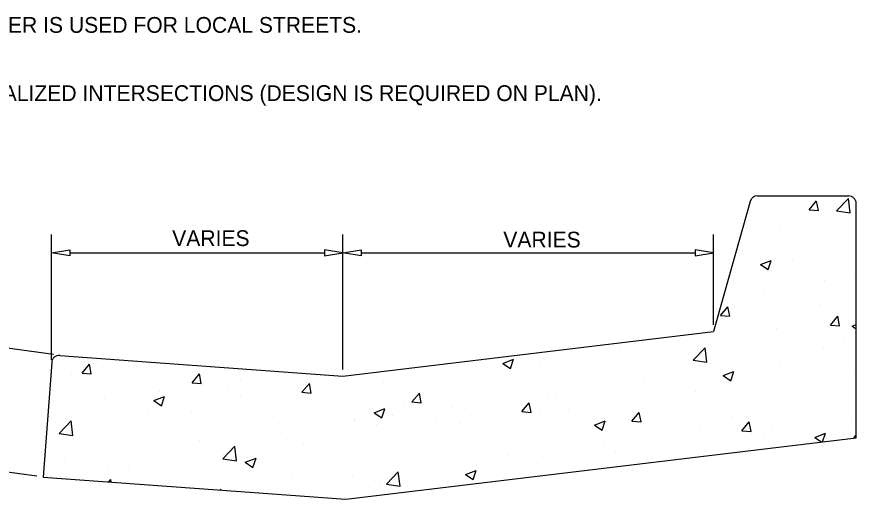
# Model space of a CAD drawing. Extents: x 6712067 to 6713867, y 1867712 to 1869162.
# Drawn here: x 6712266.7 to 6712585.9, y 1868583.6 to 1868767 of the extents above; entities that cross this region are included whole.
import ezdxf

# ---------------------------------------------------------------- set-up
doc = ezdxf.new("R2010")
doc.units = 0
for name, color, linetype in [('G-MARK', 7, 'Continuous'), ('G-TEXT', 7, 'Continuous'), ('Misc CnstDet(22)', 7, 'Continuous')]:
    doc.layers.add(name, color=color, linetype=linetype)

msp = doc.modelspace()

# ---------------------------------------------------------------- linework, layer by layer
at = {"layer": 'G-MARK'}
for p, q in [((6712279.92, 1868636.54), (6712279.92, 1868684.23)), ((6712390.72, 1868632.86), (6712390.72, 1868684.23)), ((6712531.74, 1868649.87), (6712531.74, 1868684.23)), ((6712286.92, 1868677.23), (6712383.72, 1868677.23)), ((6712397.72, 1868677.23), (6712524.74, 1868677.23)), ((6712280.72, 1868638.6), (6712254.9, 1868642.11)), ((6712274.41, 1868592.29), (6712248.59, 1868595.82))]:
    msp.add_line(p, q, dxfattribs=at)
at = {"layer": 'G-TEXT'}
for points in [[(6712286.92, 1868678.4), (6712286.92, 1868676.06), (6712279.92, 1868677.23)], [(6712383.72, 1868678.4), (6712383.72, 1868676.06), (6712390.72, 1868677.23)], [(6712397.72, 1868678.4), (6712397.72, 1868676.06), (6712390.72, 1868677.23)], [(6712524.74, 1868678.4), (6712524.74, 1868676.06), (6712531.74, 1868677.23)]]:
    msp.add_lwpolyline(points, close=True, dxfattribs=at)
at = {"layer": 'Misc CnstDet(22)'}
for p, q in [((6712548.37, 1868698.93), (6712583.03, 1868698.93)), ((6712578.48, 1868693.21), (6712583.03, 1868697.94)), ((6712583.67, 1868692.41), (6712583.03, 1868697.94)), ((6712545.57, 1868696.79), (6712531.73, 1868647.4)), ((6712551.38, 1868696.93), (6712551.38, 1868696.93)), ((6712568.08, 1868693.63), (6712570.88, 1868696.98)), ((6712571.57, 1868693.3), (6712570.88, 1868696.95)), ((6712585.94, 1868606.96), (6712585.94, 1868696.01)), ((6712568.08, 1868693.63), (6712571.57, 1868693.3)), ((6712578.48, 1868693.21), (6712583.67, 1868692.41)), ((6712557.14, 1868687.13), (6712557.14, 1868687.13)), ((6712390.72, 1868632.86), (6712390.72, 1868684.23)), ((6712571.21, 1868680.31), (6712571.21, 1868680.31)), ((6712572.86, 1868678.8), (6712572.86, 1868678.8)), ((6712390.72, 1868677.23), (6712390.72, 1868677.23)), ((6712531.74, 1868677.23), (6712531.74, 1868677.23)), ((6712549.56, 1868672.83), (6712553.65, 1868674.39)), ((6712549.56, 1868672.83), (6712552.45, 1868670.88)), ((6712552.45, 1868670.88), (6712553.65, 1868674.39)), ((6712561.61, 1868674.55), (6712561.61, 1868674.55)), ((6712542.79, 1868668.04), (6712542.79, 1868668.04)), ((6712556.43, 1868667.71), (6712556.43, 1868667.71)), ((6712573.89, 1868666.73), (6712573.89, 1868666.73)), ((6712585.18, 1868667.51), (6712585.18, 1868667.51)), ((6712551.19, 1868661.68), (6712551.19, 1868661.68)), ((6712534.37, 1868653.44), (6712537.17, 1868656.77)), ((6712537.83, 1868653.12), (6712537.17, 1868656.77)), ((6712572.1, 1868657.73), (6712572.1, 1868657.73)), ((6712534.37, 1868653.44), (6712537.83, 1868653.12)), ((6712557.5, 1868655.8), (6712557.5, 1868655.8)), ((6712576.16, 1868649.77), (6712578.99, 1868653.12)), ((6712579.65, 1868649.47), (6712578.99, 1868653.12)), ((6712576.16, 1868649.77), (6712579.65, 1868649.47)), ((6712584.36, 1868649.35), (6712585.94, 1868649.97)), ((6712585.64, 1868652.43), (6712585.64, 1868652.43)), ((6712390.72, 1868630.4), (6712531.73, 1868647.4)), ((6712531.74, 1868647.41), (6712531.74, 1868647.41)), ((6712555.71, 1868648.32), (6712555.71, 1868648.32)), ((6712584.36, 1868649.35), (6712585.94, 1868648.3)), ((6712525.44, 1868643.94), (6712525.44, 1868643.94)), ((6712550.02, 1868644.92), (6712550.02, 1868644.92)), ((6712581.12, 1868643.59), (6712581.12, 1868643.59)), ((6712496, 1868640.22), (6712496, 1868640.22)), ((6712524, 1868636.43), (6712528.54, 1868641.16)), ((6712529.18, 1868635.63), (6712528.54, 1868641.16)), ((6712573.45, 1868641.27), (6712573.45, 1868641.27)), ((6712283.12, 1868638.25), (6712390.72, 1868630.4)), ((6712283.13, 1868638.26), (6712283.13, 1868638.26)), ((6712578.85, 1868637.63), (6712578.85, 1868637.63)), ((6712280.03, 1868635.56), (6712276.84, 1868591.95)), ((6712279.92, 1868634.1), (6712279.92, 1868634.1)), ((6712291.57, 1868631.52), (6712294.37, 1868634.87)), ((6712295.06, 1868631.22), (6712294.37, 1868634.87)), ((6712299.24, 1868633.63), (6712299.24, 1868633.63)), ((6712317.39, 1868635.19), (6712317.39, 1868635.19)), ((6712451.58, 1868635.22), (6712455.67, 1868636.8)), ((6712451.58, 1868635.22), (6712454.5, 1868633.26)), ((6712454.5, 1868633.26), (6712455.67, 1868636.8)), ((6712466.07, 1868636.11), (6712466.07, 1868636.11)), ((6712524, 1868636.43), (6712529.18, 1868635.63)), ((6712539.46, 1868635.45), (6712539.46, 1868635.45)), ((6712556.77, 1868634.73), (6712556.77, 1868634.73)), ((6712287.46, 1868631.11), (6712287.46, 1868631.11)), ((6712291.57, 1868631.52), (6712295.06, 1868631.22)), ((6712333.39, 1868627.87), (6712336.19, 1868631.22)), ((6712336.88, 1868627.55), (6712336.19, 1868631.22)), ((6712373.71, 1868631.61), (6712373.71, 1868631.61)), ((6712435.77, 1868631.73), (6712435.77, 1868631.73)), ((6712535.38, 1868630.56), (6712539.46, 1868632.12)), ((6712535.38, 1868630.56), (6712538.27, 1868628.61)), ((6712538.27, 1868628.61), (6712539.46, 1868632.12)), ((6712542.17, 1868632.81), (6712542.17, 1868632.81)), ((6712584.93, 1868633.01), (6712584.93, 1868633.01)), ((6712333.39, 1868627.87), (6712336.88, 1868627.57)), ((6712351.63, 1868628.7), (6712351.63, 1868628.7)), ((6712375.2, 1868624.22), (6712378, 1868627.55)), ((6712378.67, 1868623.9), (6712378, 1868627.55)), ((6712390.72, 1868630.41), (6712390.72, 1868630.41)), ((6712390.72, 1868630.41), (6712390.72, 1868630.41)), ((6712406.33, 1868628.01), (6712406.33, 1868628.01)), ((6712505.36, 1868627.96), (6712505.36, 1868627.96)), ((6712505.45, 1868629.59), (6712505.45, 1868629.59)), ((6712555, 1868628.9), (6712555, 1868628.9)), ((6712289.71, 1868625.64), (6712289.71, 1868625.64)), ((6712320.83, 1868624.34), (6712320.83, 1868624.34)), ((6712337.06, 1868626.77), (6712337.06, 1868626.77)), ((6712347.2, 1868626.65), (6712347.2, 1868626.65)), ((6712375.2, 1868624.22), (6712378.67, 1868623.9)), ((6712483.28, 1868625.05), (6712483.28, 1868625.05)), ((6712524.73, 1868624.54), (6712524.73, 1868624.54)), ((6712300.22, 1868621.93), (6712300.22, 1868621.93)), ((6712318.84, 1868621.1), (6712322.92, 1868622.66)), ((6712318.84, 1868621.1), (6712321.73, 1868619.13)), ((6712321.73, 1868619.13), (6712322.92, 1868622.66)), ((6712351.93, 1868623.03), (6712351.93, 1868623.03)), ((6712376.4, 1868623.9), (6712376.4, 1868623.9)), ((6712383.05, 1868621.7), (6712383.05, 1868621.7)), ((6712417, 1868620.55), (6712419.82, 1868623.9)), ((6712420.49, 1868620.25), (6712419.82, 1868623.9)), ((6712468.68, 1868623.12), (6712468.68, 1868623.12)), ((6712471.46, 1868623.76), (6712471.46, 1868623.76)), ((6712301.99, 1868617.82), (6712301.99, 1868617.82)), ((6712313.21, 1868620.83), (6712313.21, 1868620.83)), ((6712346.13, 1868619.52), (6712346.13, 1868619.52)), ((6712402.61, 1868616.42), (6712406.69, 1868618)), ((6712405.52, 1868614.47), (6712406.69, 1868617.98)), ((6712414.17, 1868620.39), (6712414.17, 1868620.39)), ((6712417, 1868620.55), (6712420.49, 1868620.25)), ((6712431.87, 1868618.28), (6712431.87, 1868618.28)), ((6712437.47, 1868617.93), (6712437.47, 1868617.93)), ((6712445.3, 1868619.08), (6712445.3, 1868619.08)), ((6712458.81, 1868616.9), (6712461.64, 1868620.25)), ((6712462.3, 1868616.58), (6712461.64, 1868620.23)), ((6712476.42, 1868617.75), (6712476.42, 1868617.75)), ((6712495.28, 1868620.8), (6712495.28, 1868620.8)), ((6712279.2, 1868615), (6712279.2, 1868615)), ((6712316.68, 1868615.8), (6712316.68, 1868615.8)), ((6712333.11, 1868616.51), (6712333.11, 1868616.51)), ((6712364.23, 1868615.18), (6712364.23, 1868615.18)), ((6712402.61, 1868616.42), (6712405.52, 1868614.47)), ((6712409.79, 1868615.39), (6712409.79, 1868615.39)), ((6712458.81, 1868616.9), (6712462.3, 1868616.58)), ((6712465.36, 1868616.69), (6712465.36, 1868616.69)), ((6712500.63, 1868613.23), (6712503.45, 1868616.58)), ((6712504.12, 1868612.93), (6712503.45, 1868616.58)), ((6712507.54, 1868616.44), (6712507.54, 1868616.44)), ((6712538.66, 1868615.13), (6712538.66, 1868615.13)), ((6712563.52, 1868614.65), (6712563.52, 1868614.65)), ((6712282.85, 1868608.59), (6712287.39, 1868613.32)), ((6712286.75, 1868611.69), (6712286.75, 1868611.69)), ((6712288.04, 1868607.79), (6712287.39, 1868613.32)), ((6712395.19, 1868613.46), (6712395.19, 1868613.46)), ((6712395.35, 1868613.87), (6712395.35, 1868613.87)), ((6712403.46, 1868612.08), (6712403.46, 1868612.08)), ((6712426.48, 1868612.56), (6712426.48, 1868612.56)), ((6712435.08, 1868612.33), (6712435.08, 1868612.33)), ((6712486.4, 1868611.76), (6712490.46, 1868613.32)), ((6712486.4, 1868611.76), (6712489.29, 1868609.81)), ((6712489.29, 1868609.79), (6712490.46, 1868613.32)), ((6712500.63, 1868613.23), (6712504.12, 1868612.93)), ((6712541.44, 1868611.74), (6712541.44, 1868611.74)), ((6712542.45, 1868609.58), (6712545.25, 1868612.93)), ((6712545.94, 1868609.26), (6712545.25, 1868612.93)), ((6712569.78, 1868613.83), (6712569.78, 1868613.83)), ((6712584.22, 1868613.6), (6712584.22, 1868613.6)), ((6712282.85, 1868608.59), (6712288.04, 1868607.79)), ((6712358.38, 1868608.62), (6712358.38, 1868608.62)), ((6712405.64, 1868608.59), (6712405.64, 1868608.59)), ((6712457.6, 1868611.25), (6712457.6, 1868611.25)), ((6712488.72, 1868609.92), (6712488.72, 1868609.92)), ((6712519.84, 1868608.62), (6712519.84, 1868608.62)), ((6712526.84, 1868609.81), (6712526.84, 1868609.81)), ((6712542.45, 1868609.58), (6712545.94, 1868609.28)), ((6712554.29, 1868609.51), (6712554.29, 1868609.51)), ((6712570.17, 1868607.08), (6712574.26, 1868608.66)), ((6712573.18, 1868605.43), (6712574.26, 1868608.64)), ((6712336.3, 1868605.7), (6712336.3, 1868605.7)), ((6712369.47, 1868606.25), (6712369.47, 1868606.25)), ((6712391.82, 1868583.55), (6712585.94, 1868606.96)), ((6712490.03, 1868604.97), (6712490.03, 1868604.97)), ((6712524.02, 1868605.13), (6712524.02, 1868605.13)), ((6712550.94, 1868607.31), (6712550.94, 1868607.31)), ((6712570.17, 1868607.08), (6712572.72, 1868605.38)), ((6712571.04, 1868606.48), (6712571.04, 1868606.48)), ((6712585.04, 1868606.85), (6712585.94, 1868607.93)), ((6712321.71, 1868603.77), (6712321.71, 1868603.77)), ((6712345.07, 1868598.93), (6712349.61, 1868603.68)), ((6712350.26, 1868598.13), (6712349.61, 1868603.66)), ((6712375.69, 1868604.48), (6712375.69, 1868604.48)), ((6712467.95, 1868602.05), (6712467.95, 1868602.05)), ((6712284.89, 1868598.93), (6712284.89, 1868598.93)), ((6712335.48, 1868600.42), (6712335.48, 1868600.42)), ((6712345.07, 1868598.93), (6712350.26, 1868598.13)), ((6712345.41, 1868600.12), (6712345.41, 1868600.12)), ((6712353.63, 1868597.62), (6712357.72, 1868599.18)), ((6712356.52, 1868595.67), (6712357.72, 1868599.18)), ((6712453.35, 1868600.15), (6712453.35, 1868600.15)), ((6712494.57, 1868601.41), (6712494.57, 1868601.41)), ((6712278.1, 1868596.02), (6712278.1, 1868596.02)), ((6712315.97, 1868596.38), (6712315.97, 1868596.38)), ((6712353.63, 1868597.62), (6712356.52, 1868595.67)), ((6712464.64, 1868597.3), (6712464.64, 1868597.3)), ((6712286.04, 1868592.27), (6712286.04, 1868592.27)), ((6712301.49, 1868594.59), (6712301.49, 1868594.59)), ((6712309.22, 1868594.71), (6712309.22, 1868594.71)), ((6712340.34, 1868593.38), (6712340.34, 1868593.38)), ((6712394.46, 1868592.39), (6712394.46, 1868592.39)), ((6712407.29, 1868589.29), (6712411.83, 1868594.02)), ((6712412.48, 1868588.49), (6712411.83, 1868594.02)), ((6712416.54, 1868595.28), (6712416.54, 1868595.28)), ((6712434.37, 1868592.92), (6712434.37, 1868592.92)), ((6712437.4, 1868592.96), (6712441.49, 1868594.52)), ((6712437.4, 1868592.96), (6712440.32, 1868590.99)), ((6712440.32, 1868590.99), (6712441.49, 1868594.52)), ((6712276.84, 1868591.96), (6712276.84, 1868591.96)), ((6712276.84, 1868591.95), (6712391.82, 1868583.55)), ((6712301.71, 1868590.14), (6712302.47, 1868591.03)), ((6712302.63, 1868590.07), (6712302.47, 1868591.01)), ((6712371.46, 1868592.07), (6712371.46, 1868592.07)), ((6712379.86, 1868590.46), (6712379.86, 1868590.46)), ((6712402.58, 1868590.76), (6712402.58, 1868590.76)), ((6712404.93, 1868589.2), (6712404.93, 1868589.2)), ((6712407.29, 1868589.29), (6712412.48, 1868588.49)), ((6712433.71, 1868589.45), (6712433.71, 1868589.45)), ((6712344.01, 1868587.04), (6712344.29, 1868587.36)), ((6712344.33, 1868587.02), (6712344.29, 1868587.36)), ((6712375, 1868585.09), (6712375, 1868585.09))]:
    msp.add_line(p, q, dxfattribs=at)
for centre, start, end in [((6712548.37, 1868696.01), 90, 164.348), ((6712583.03, 1868696.01), 0, 90), ((6712282.92, 1868635.35), 85.8258, 175.8258)]:
    msp.add_arc(centre, 2.91, start, end, dxfattribs=at)

# ---------------------------------------------------------------- texts
for s, p in [("8' CROSS GUTTER IS USED FOR LOCAL STREETS.", (6712202.56, 1868760.94)), ('FOR NON SIGNALIZED INTERSECTIONS (DESIGN IS REQUIRED ON PLAN).', (6712202.56, 1868734.99)), ('VARIES', (6712325.84, 1868679.83)), ('VARIES', (6712451.75, 1868679.29))]:
    msp.add_text(s, height=6, dxfattribs=at).set_placement(p)

doc.saveas('drawing.dxf')
